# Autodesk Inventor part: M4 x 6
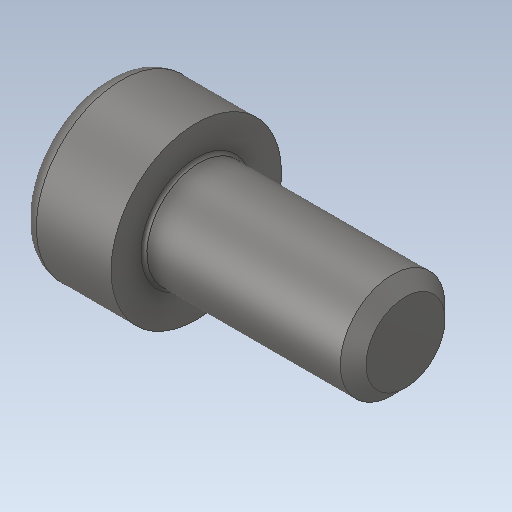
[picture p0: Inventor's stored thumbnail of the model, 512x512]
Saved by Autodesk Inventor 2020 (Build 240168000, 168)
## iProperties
Created: 2015-11
Part Number: M4 x 6
Material: Ogólny
Document SubType Name: Modeling
Designer: Tomasz
Density: 1 g/cm^3
Appearance: Domyślna
Sending System: SolidWorks 2017
Last Author: Tomasz
Last Saved: 2017-10-01
Author: Tomasz
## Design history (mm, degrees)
feature "Imported1"
node "Bryła1"
